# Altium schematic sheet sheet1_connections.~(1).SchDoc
size A3; SheetNumber: 3; SheetTotal: 4
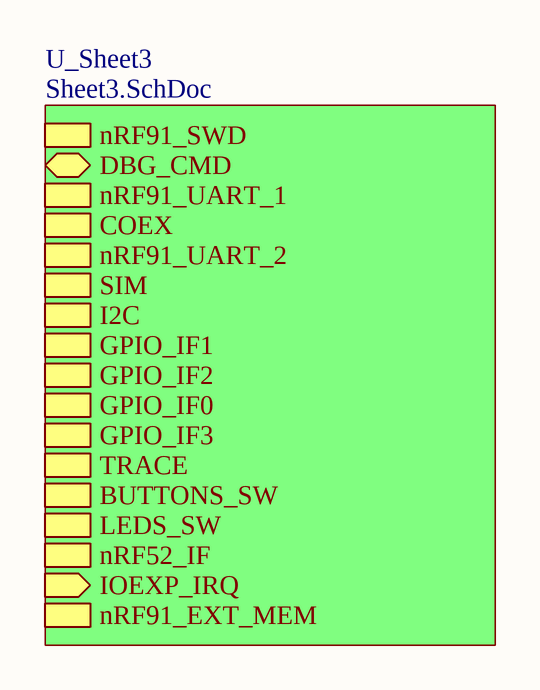
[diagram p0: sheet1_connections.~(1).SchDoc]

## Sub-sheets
U_Sheet3 = Sheet3.SchDoc: nRF91_SWD (harness SWD), DBG_CMD (bidir), nRF91_UART_1 (harness UART), COEX (harness COEX), nRF91_UART_2 (harness UART), SIM (harness SIM), I2C (harness I2C), GPIO_IF1 (harness GPIO_IF1), GPIO_IF2 (harness GPIO_IF2), GPIO_IF0 (harness GPIO_IF0), GPIO_IF3 (harness GPIO_IF3), TRACE (harness TRACE), BUTTONS_SW (harness UI), LEDS_SW (harness UI), nRF52_IF (harness nRF_IF), IOEXP_IRQ (in), nRF91_EXT_MEM (harness MEMORY)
